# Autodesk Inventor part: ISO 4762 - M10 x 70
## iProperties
Comments: To add or edit properties for Autodesk Inventor files, use iProperties.
Created: 2004-03
Part Number: ISO 4762 - M10 x 70
Vendor: Autodesk Inc.
Document SubType Name: Modeling
Designer: rak
Material: Default
Description: Hexagon Socket Head Cap Screw
Standard: ISO 4762
Size Designation: M10 x 70
Alert: To add or edit properties for Autodesk Inventor files, use iProperties.
Control State: 0
Master: False
Checked Out: False
Shininess: 64.0
Length Units: 11269
Angle Units: 11279
Time Units: 11290
Mass Units: 11283
Length Display Precision: 3
Angle Display Precision: 2
Compacted: True
EGR: 1
Density: 0.0
Volumn: 0.0
Area: 0.0
PropertySet Name: Model Information
Author: rak
Revision Number: 8
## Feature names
1. Body [Revolution]
2. Slot [Extrusion]
3. Fillet1
4. Chamfer1
